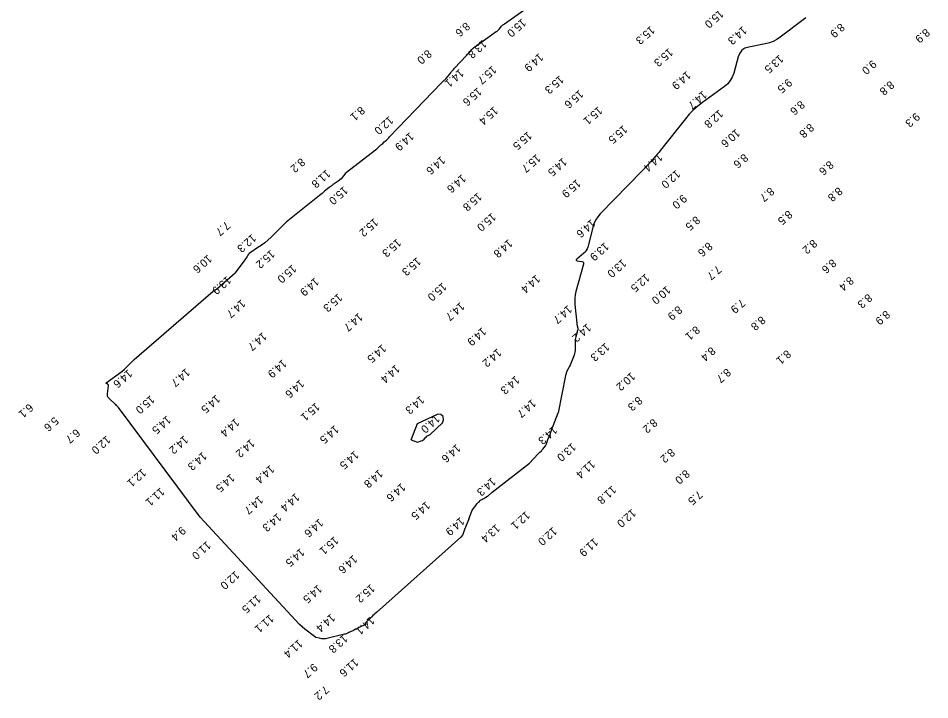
# Model space of a CAD drawing. Extents: x 824616 to 827440, y 158441 to 163197.
# Drawn here: x 824879 to 825448, y 158441 to 158867 of the extents above; entities that cross this region are included whole.
import ezdxf

# ---------------------------------------------------------------- set-up
doc = ezdxf.new("R2010")
doc.units = 0
doc.layers.add('V-CHAN-CONT-EL14', color=7, linetype='Continuous')
doc.layers.add('V-TOPO-SOUN', color=7, linetype='Continuous')

msp = doc.modelspace()

# ---------------------------------------------------------------- linework, layer by layer
at = {"layer": 'V-CHAN-CONT-EL14'}
for points in [[(825083.08, 158770.32), (825102.8, 158785.49), (825105.4, 158787.97), (825106.65, 158788.84), (825107.42, 158789.79), (825108.09, 158790.27), (825108.85, 158790.86), (825109.28, 158791.34), (825109.85, 158791.82), (825110.27, 158792.25), (825110.8, 158792.98), (825143.18, 158826.61), (825143.4, 158826.84), (825143.62, 158827.06), (825143.85, 158827.28), (825144.09, 158827.49), (825145.03, 158828.32), (825145.26, 158828.54), (825145.49, 158828.76), (825145.7, 158828.99), (825145.9, 158829.23), (825149, 158832.99), (825149.59, 158833.7), (825150.19, 158834.39), (825150.8, 158835.08), (825151.42, 158835.75), (825158.72, 158843.58), (825159.16, 158844.06), (825159.6, 158844.54), (825160.03, 158845.02), (825160.46, 158845.5), (825162.18, 158847.45), (825162.62, 158847.92), (825163.08, 158848.36), (825163.57, 158848.78), (825164.09, 158849.17), (825177.52, 158858.7), (825177.99, 158859.05), (825178.44, 158859.43), (825178.86, 158859.83), (825179.26, 158860.26), (825180.81, 158862.02), (825181.21, 158862.44), (825181.63, 158862.85), (825182.08, 158863.22), (825182.54, 158863.58), (825214.67, 158886.43)], [(825370.96, 158867.21), (825355.01, 158855.13), (825352.85, 158853.68), (825350.57, 158852.5), (825348.17, 158851.6), (825345.64, 158850.98), (825335.28, 158849.03), (825332.93, 158848.28), (825331.05, 158847.03), (825329.64, 158845.26), (825328.71, 158842.97), (825325.87, 158832.68), (825324.99, 158830.24), (825323.74, 158828.06), (825322.13, 158826.13), (825320.15, 158824.44), (825306.35, 158814.47), (825303.42, 158812.2), (825300.67, 158809.74), (825298.1, 158807.09), (825295.7, 158804.26), (825280.13, 158784.51), (825279.24, 158783.39), (825278.32, 158782.29), (825277.39, 158781.19), (825276.44, 158780.12), (825272.62, 158775.84), (825271.66, 158774.77), (825270.68, 158773.72), (825269.7, 158772.67), (825268.7, 158771.64), (825242.5, 158744.78), (825240.9, 158742.91), (825239.57, 158740.88), (825238.53, 158738.69), (825237.77, 158736.34), (825234.66, 158724.09), (825234.29, 158722.98), (825233.76, 158721.97), (825233.07, 158721.06), (825232.23, 158720.25), (825227.82, 158716.6), (825227.42, 158716.18), (825227.34, 158715.85), (825227.58, 158715.61), (825228.13, 158715.46), (825230.99, 158715.03), (825231.59, 158714.85), (825231.96, 158714.52), (825232.11, 158714.05), (825232.03, 158713.42), (825227.31, 158696.3), (825226.85, 158694.28), (825226.58, 158692.25), (825226.51, 158690.2), (825226.62, 158688.14), (825227.8, 158676.48), (825227.85, 158676.09), (825227.9, 158675.71), (825227.97, 158675.33), (825228.04, 158674.95), (825228.37, 158673.44), (825228.43, 158673.06), (825228.45, 158672.69), (825228.41, 158672.31), (825228.33, 158671.94), (825227.22, 158667.92), (825227.03, 158667.13), (825226.89, 158666.32), (825226.81, 158665.51), (825226.78, 158664.69), (825226.77, 158660.44), (825226.73, 158659.47), (825226.6, 158658.51), (825226.38, 158657.57), (825226.08, 158656.64), (825223.65, 158650.2), (825223.08, 158649.15), (825222.43, 158647.95), (825221.69, 158646.52), (825220.86, 158643.89), (825216.24, 158620.43)], [(825083.49, 158770.49), (825080.53, 158766.72), (825078.63, 158765.19), (825077.42, 158764.47), (825076.28, 158763.64), (825075.66, 158763.15), (825075.12, 158762.74), (825074.71, 158762.46), (825074.25, 158762.08), (825073.72, 158761.72), (825073.02, 158761.32), (825070.05, 158758.99), (825069.53, 158758.45), (825068.6, 158757.62), (825066.99, 158756.27), (825062.93, 158752.94), (825046.16, 158739.62)], [(825046.16, 158739.62), (825036.86, 158730.32), (825032.93, 158726.78), (825030.7, 158725.21), (825029.9, 158724.71), (825029.15, 158724.32), (825023.13, 158720.09), (825022.59, 158719.59), (825022.27, 158719.05), (825021.73, 158718.2), (825020.38, 158716.09), (825014.36, 158707.93)], [(824951.1, 158653.92), (825000.51, 158696.51), (825000.45, 158696.64), (825000.45, 158696.7), (825000.57, 158696.77), (825001.13, 158697.07), (825002.57, 158697.76), (825014.36, 158707.93)], [(824992.48, 158555.36), (824941.35, 158623.91), (824940.19, 158625.11), (824939.7, 158625.62), (824939.49, 158625.79), (824939.27, 158625.95), (824935.5, 158629.48), (824934.95, 158630.12), (824934.6, 158630.83), (824934.44, 158631.61), (824934.47, 158632.45), (824935.23, 158637.45), (824935.24, 158637.57), (824935.22, 158637.69), (824935.18, 158637.8), (824935.11, 158637.91), (824934.78, 158638.31), (824934.7, 158638.4), (824934.6, 158638.48), (824934.5, 158638.55), (824934.38, 158638.61), (824933.7, 158638.9), (824933.58, 158638.97), (824933.54, 158639.04), (824933.56, 158639.13), (824933.66, 158639.22), (824943.51, 158646.3), (824945.24, 158647.79), (824951.1, 158653.92)], [(825124.25, 158603.6), (825128.19, 158613.9), (825140.68, 158619.72)], [(825124.25, 158603.6), (825128.33, 158602.25), (825130.5, 158603.05), (825131.31, 158603.26), (825132.42, 158604.06), (825133.01, 158604.79), (825133.62, 158605.33), (825134.06, 158605.92), (825134.92, 158606.31), (825136.25, 158606.94), (825143.8, 158614.18), (825144.57, 158616.15), (825144.24, 158618.13), (825142.88, 158619.4), (825140.68, 158619.72)], [(825198.22, 158589.08), (825203.57, 158594.61), (825204.76, 158595.98), (825205.84, 158596.81), (825206.06, 158597.16), (825206.61, 158597.79), (825208.18, 158599.94), (825208.87, 158601.22), (825209.98, 158604.44), (825210.91, 158606.42), (825211.99, 158609.64), (825216.24, 158620.43)], [(825160.29, 158554.16), (825162.38, 158559.62), (825164.68, 158562.57), (825165.29, 158563.73), (825165.76, 158564.11), (825166.34, 158564.62), (825166.92, 158565.21), (825167.18, 158565.73), (825168.4, 158566.34), (825169.07, 158566.75), (825169.63, 158567.07), (825170.9, 158567.88), (825171.91, 158568.39), (825172.12, 158568.42), (825172.45, 158568.72), (825174.94, 158570.91), (825198.22, 158589.08)], [(825160.29, 158554.16), (825157.7, 158547.59), (825157.12, 158546.37), (825156.73, 158545.14), (825156.49, 158544.03), (825155.4, 158542.76), (825102.58, 158495.87), (825101.84, 158495.2), (825101.11, 158494.53), (825100.39, 158493.85), (825099.68, 158493.16), (825095.61, 158489.18), (825095.54, 158489.09), (825095.53, 158489.02), (825095.57, 158488.95), (825095.66, 158488.89), (825096.12, 158488.68), (825096.21, 158488.62), (825096.24, 158488.57), (825096.21, 158488.51), (825096.13, 158488.46), (825091.01, 158485.97), (825090.31, 158485.63), (825089.61, 158485.29), (825088.92, 158484.94), (825088.22, 158484.59), (825085.45, 158483.18), (825084.75, 158482.85), (825084.03, 158482.57), (825083.3, 158482.32), (825082.55, 158482.13), (825070.83, 158479.38), (825070.18, 158479.31), (825069.52, 158479.25), (825068.57, 158479.32), (825066.98, 158479.67), (825064.7, 158480.19), (825061.41, 158482.67), (825060.29, 158483.54), (825057.88, 158485.45), (825054.49, 158488.34), (824992.48, 158555.36)]]:
    msp.add_lwpolyline(points, dxfattribs=at)

# ---------------------------------------------------------------- texts
at = {"layer": 'V-TOPO-SOUN'}
for s, p in [('15.0 ', (825317, 158872.68)), ('15.0 ', (825193.51, 158867.08)), ('8.6', (825158.42, 158864.88)), ('15.3 ', (825273.96, 158862.5)), ('14.3 ', (825331.5, 158862.32)), ('8.9', (825392.57, 158864.22)), ('8.9', (825445.82, 158860.95)), ('13.8 ', (825168.93, 158853.81)), ('15.3 ', (825285.34, 158848.62)), ('8.0', (825134.49, 158847.71)), ('14.9 ', (825204.31, 158845.48)), ('13.5 ', (825354.39, 158844.49)), ('15.7 ', (825175.04, 158837.68)), ('9.0', (825412.48, 158841.23)), ('14.1 ', (825154.58, 158835.66)), ('15.3 ', (825217.1, 158831.6)), ('14.9 ', (825296.47, 158834.3)), ('9.5', (825359.71, 158829.63)), ('8.8', (825423.54, 158828.26)), ('15.6 ', (825165.82, 158824.05)), ('15.6 ', (825229.34, 158822.55)), ('14.7 ', (825306.52, 158822.04)), ('8.6', (825367.63, 158815.9)), ('8.1', (825092.73, 158812.28)), ('15.4 ', (825176, 158812.19)), ('15.1 ', (825241.24, 158812.24)), ('12.8 ', (825316.73, 158810.23)), ('9.3', (825439.6, 158808.34)), ('12.0 ', (825110.61, 158806.16)), ('15.5 ', (825197.15, 158796.59)), ('15.5 ', (825256.84, 158800.46)), ('10.6 ', (825327.23, 158798.15)), ('8.8', (825373.38, 158801.61)), ('14.9 ', (825123.43, 158796.04)), ('8.2', (825055.36, 158780)), ('14.6 ', (825143.01, 158781.15)), ('15.7 ', (825202.56, 158782.43)), ('14.5 ', (825219.01, 158780.14)), ('14.4 ', (825278.85, 158783.04)), ('8.6', (825332.22, 158782.74)), ('8.6', (825385.67, 158778.34)), ('11.8 ', (825071.32, 158772.77)), ('14.6 ', (825155.94, 158769.78)), ('12.0 ', (825289.9, 158772.59)), ('15.0 ', (825082.18, 158762.36)), ('15.9 ', (825227.68, 158766.73)), ('15.8 ', (825165.9, 158758.35)), ('9.0', (825293.98, 158757.25)), ('8.7', (825348.59, 158761.75)), ('8.8', (825391.18, 158761.87)), ('15.0 ', (825174.7, 158745.74)), ('8.5', (825359.89, 158747.32)), ('7.7', (825008.57, 158740.45)), ('15.2 ', (825101.12, 158742.41)), ('14.6 ', (825236.82, 158741.75)), ('8.5', (825302.2, 158743.79)), ('12.3 ', (825024.83, 158732.52)), ('15.3 ', (825115.45, 158729.62)), ('14.8 ', (825185.08, 158729.23)), ('8.2', (825375.36, 158729.16)), ('15.2 ', (825036.53, 158722.58)), ('13.9 ', (825245.26, 158727.3)), ('8.6', (825309.97, 158727.45)), ('10.6 ', (824997.21, 158719.62)), ('15.3 ', (825127.83, 158717.95)), ('13.0 ', (825256.19, 158716.85)), ('15.0 ', (825049.96, 158713.42)), ('7.7', (825315.56, 158712.91)), ('8.6', (825387.35, 158716.95)), ('13.9 ', (825009.18, 158706.27)), ('14.4 ', (825202.32, 158707.09)), ('12.5 ', (825270.78, 158707.74)), ('8.4', (825398.24, 158705.99)), ('14.9 ', (825064.11, 158705.29)), ('15.0 ', (825143.87, 158702.15)), ('10.0 ', (825283.9, 158700.14)), ('15.3 ', (825078.69, 158695.37)), ('8.3', (825409.76, 158695.23)), ('14.7 ', (825018.15, 158691.64)), ('14.7 ', (825155.04, 158689.9)), ('7.9', (825330.44, 158692.01)), ('14.7 ', (825091.44, 158683.21)), ('14.7 ', (825222.26, 158688.06)), ('8.9', (825291.06, 158687.72)), ('8.9', (825420.94, 158684.82)), ('8.8', (825343.08, 158681.3)), ('14.7 ', (825031.44, 158671.13)), ('14.9 ', (825168.63, 158674.18)), ('14.2 ', (825234.18, 158676.6)), ('8.1', (825302.1, 158675.16)), ('14.5 ', (825106.13, 158663.6)), ('14.2 ', (825178.13, 158660.97)), ('13.3 ', (825245.65, 158664.53)), ('8.4', (825311.82, 158662.06)), ('8.1', (825359.01, 158660.12)), ('14.9 ', (825043.92, 158654.16)), ('14.7 ', (824983.46, 158648.64)), ('14.4 ', (825114.6, 158650.9)), ('14.6 ', (824947.4, 158647.92)), ('14.3 ', (825189.48, 158643.94)), ('10.2 ', (825261.74, 158646.14)), ('8.7', (825321.5, 158648.64)), ('14.6 ', (825054.89, 158641.58)), ('15.0 ', (824961.39, 158631.71)), ('14.5 ', (825002.31, 158632.05)), ('14.3 ', (825129.97, 158631.49)), ('6.1', (824885.47, 158626.64)), ('15.1 ', (825064.59, 158627.18)), ('14.7 ', (825199.71, 158629.32)), ('8.3', (825266.16, 158631.1)), ('5.6', (824901.32, 158618.32)), ('14.5 ', (824971.59, 158619.02)), ('14.4 ', (825014.36, 158617.36)), ('14.0 ', (825139.65, 158619.65)), ('8.2', (825275.5, 158617.18)), ('6.7', (824914.79, 158610.88)), ('14.5 ', (825076.47, 158613.05)), ('14.3 ', (825212.99, 158612.55)), ('12.0 ', (824933.85, 158606.53)), ('14.2 ', (824982.36, 158606.61)), ('14.2 ', (825023.95, 158604.41)), ('14.5 ', (825088.92, 158597.06)), ('14.6 ', (825152.62, 158601.26)), ('13.0 ', (825224.72, 158602)), ('8.2', (825286.49, 158598.6)), ('14.3 ', (824993.96, 158596.36)), ('12.1 ', (824956.09, 158585.98)), ('14.4 ', (825036.21, 158588.19)), ('11.4 ', (825236.67, 158591.29)), ('14.5 ', (825011.44, 158582.71)), ('14.8 ', (825104.06, 158585.4)), ('14.3 ', (825174.64, 158580.37)), ('8.0', (825295.72, 158585.32)), ('14.6 ', (825118.18, 158576.88)), ('11.8 ', (825249.87, 158575.3)), ('11.1 ', (824967.62, 158574.06)), ('14.7 ', (825029.19, 158568.99)), ('14.4 ', (825051.98, 158570.63)), ('7.5', (825303.77, 158572.32)), ('14.5 ', (825133.59, 158565.51)), ('14.3 ', (825040.65, 158558.12)), ('12.1 ', (825195.99, 158559.37)), ('12.0 ', (825262.2, 158560.77)), ('14.6 ', (825066.8, 158554.63)), ('14.9 ', (825155.04, 158555.65)), ('9.4', (824980.8, 158549.8)), ('13.4 ', (825177.27, 158551.26)), ('12.0 ', (825212.81, 158549.45)), ('11.0 ', (824996.54, 158540.64)), ('15.1 ', (825076.29, 158543.62)), ('11.9 ', (825238.58, 158542.58)), ('14.5 ', (825055.12, 158536.22)), ('14.6 ', (825088.05, 158531.96)), ('12.0 ', (825014.36, 158522)), ('14.5 ', (825065.98, 158513.4)), ('15.2 ', (825098.99, 158513.72)), ('11.5 ', (825027.78, 158507.13)), ('11.1 ', (825035.87, 158494.86)), ('14.4 ', (825074.19, 158495.32)), ('14.1 ', (825098.87, 158493.52)), ('11.4 ', (825053.92, 158479.24)), ('13.8 ', (825082.04, 158482.3)), ('11.6 ', (825088.79, 158467.41)), ('9.7', (825063.19, 158464.3)), ('7.2', (825070.32, 158450.44))]:
    msp.add_text(s, height=5, rotation=221.4, dxfattribs=at).set_placement(p)

doc.saveas('drawing.dxf')
